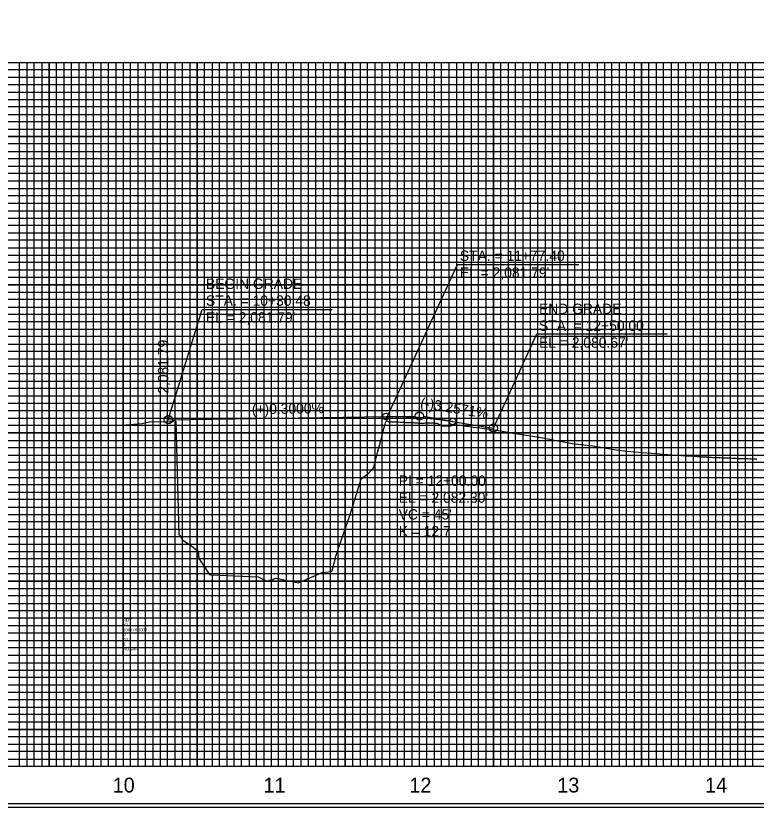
# Model space of a CAD drawing. Extents: x 757145 to 758829, y 592169 to 594973.
# Drawn here: x 757639 to 758139, y 592728 to 593262 of the extents above; entities that cross this region are included whole.
import ezdxf

# ---------------------------------------------------------------- set-up
doc = ezdxf.new("R2010")
doc.units = 0
for name, color, linetype in [('Default', 7, 'Continuous'), ('Exist CMT Alignment Centerline', 7, 'Continuous'), ('Exist CMT EOP', 7, 'Continuous'), ('Exist Vertical Profile Ground Line', 7, 'Continuous'), ('Prop CMT DNC', 7, 'Continuous'), ('Prop Dimension', 7, 'Continuous'), ('Prop Vertical Profile Curve Label', 7, 'Continuous'), ('Prop Vertical Profile Grade Label', 7, 'Continuous'), ('Scratch_Level_4', 7, 'Continuous'), ('Sheet DOT Grid CELL', 7, 'Continuous'), ('Sheet Plan And Profile CELL', 7, 'Continuous'), ('Sheet Plot Border Inside CELL', 7, 'Continuous'), ('Sheet Profile Grid Major CELL', 7, 'Continuous'), ('Sheet Profile Grid Middle CELL', 7, 'Continuous'), ('Sheet Profile Grid Minor CELL', 7, 'Continuous')]:
    doc.layers.add(name, color=color, linetype=linetype)

msp = doc.modelspace()

# ---------------------------------------------------------------- linework, layer by layer
at = {"layer": 'Default'}
for p, q in [((757889.32, 592989.23), (757937.71, 593094.1)), ((757937.71, 593094.1), (758019.68, 593094.1)), ((757742.4, 592989.28), (757765.31, 593063.71)), ((757765.31, 593063.71), (757852.97, 593063.71)), ((757961.92, 592983.68), (757991.19, 593047.13)), ((757991.19, 593047.13), (758079.26, 593047.13)), ((757742.4, 592989.28), (757742.4, 592989.28))]:
    msp.add_line(p, q, dxfattribs=at)
at = {"layer": 'Exist CMT Alignment Centerline'}
for p, q in [((757742.4, 592989.28), (757889.42, 592991.48)), ((757934.42, 592988.15), (757961.92, 592983.68))]:
    msp.add_line(p, q, dxfattribs=at)
msp.add_spline([(757889.42, 592991.48), (757890.32, 592991.49), (757891.22, 592991.5), (757892.12, 592991.51), (757893.02, 592991.51), (757893.92, 592991.51), (757894.82, 592991.5), (757895.72, 592991.5), (757896.62, 592991.49), (757897.52, 592991.47), (757898.42, 592991.46), (757899.32, 592991.44), (757900.22, 592991.41), (757901.12, 592991.39), (757902.02, 592991.36), (757902.92, 592991.32), (757903.82, 592991.29), (757904.72, 592991.25), (757905.62, 592991.21), (757906.52, 592991.16), (757907.42, 592991.11), (757908.32, 592991.06), (757909.22, 592991), (757910.12, 592990.95), (757911.02, 592990.88), (757911.92, 592990.82), (757912.82, 592990.75), (757913.72, 592990.68), (757914.62, 592990.6), (757915.52, 592990.53), (757916.42, 592990.45), (757917.32, 592990.36), (757918.22, 592990.27), (757919.12, 592990.18), (757920.02, 592990.09), (757920.92, 592989.99), (757921.82, 592989.89), (757922.72, 592989.79), (757923.62, 592989.68), (757924.52, 592989.57), (757925.42, 592989.46), (757926.32, 592989.34), (757927.22, 592989.22), (757928.12, 592989.1), (757929.02, 592988.98), (757929.92, 592988.85), (757930.82, 592988.72), (757931.72, 592988.58), (757932.62, 592988.44), (757933.52, 592988.3), (757934.42, 592988.15)], degree=3, dxfattribs=at)
at = {"layer": 'Exist CMT EOP'}
for points in [[(757711.92, 592985.24), (757712.47, 592985.41), (757714.01, 592985.74), (757721.62, 592986.47), (757724.71, 592986.74), (757729.79, 592987.81), (757743.55, 592988.08), (757745.6, 592988.13), (757746.46, 592989.13), (757747.42, 592988.01), (757749.55, 592911.52), (757750.22, 592911.44), (757751.98, 592908.18), (757758.23, 592903.97), (757762.49, 592900.64), (757762.91, 592895.54), (757770.23, 592884.8), (757771.05, 592884.7), (757803.16, 592883.34), (757809.03, 592880.24), (757815.16, 592882.44), (757830.25, 592879.11), (757846.38, 592886.07), (757852.84, 592886.82), (757855.02, 592894.95), (757855.36, 592896.53), (757856.97, 592901.21), (757865.21, 592925.3), (757869.24, 592938.45), (757872.6, 592949.31), (757877.54, 592953.17), (757879.38, 592954.93), (757879.96, 592955.48), (757880.54, 592956.03), (757881.12, 592957.05), (757881.7, 592959.28), (757882.27, 592961.5), (757882.85, 592963.72), (757883.43, 592965.92), (757884.01, 592968.11), (757884.59, 592970.3), (757885.17, 592972.48), (757885.74, 592974.66), (757886.32, 592976.83), (757886.9, 592979), (757887.48, 592981.16), (757888.06, 592983.32), (757888.63, 592985.47), (757889.31, 592987.99), (757889.79, 592988.5), (757890.37, 592988.59), (757890.95, 592987.96), (757891.53, 592987.95), (757892.1, 592987.95), (757892.68, 592987.94), (757893.26, 592987.93), (757893.84, 592987.92), (757894.42, 592987.91), (757895, 592987.91), (757895.57, 592987.9), (757896.15, 592987.89), (757896.73, 592987.88), (757897.31, 592987.87), (757897.89, 592987.82), (757899.04, 592987.62), (757899.62, 592987.59), (757900.2, 592987.56), (757900.78, 592987.53), (757901.36, 592987.52), (757901.93, 592987.5), (757902.51, 592987.49), (757903.09, 592987.47), (757903.67, 592987.46), (757904.25, 592987.44), (757904.83, 592987.43), (757905.4, 592987.41), (757905.98, 592987.39), (757906.56, 592987.37), (757907.14, 592987.35), (757907.72, 592987.33), (757908.29, 592987.29), (757908.87, 592987.25), (757909.45, 592987.21), (757910.03, 592987.16), (757910.61, 592987.12), (757911.19, 592987.08), (757911.76, 592987.04), (757912.34, 592987.03), (757912.92, 592987.03), (757913.5, 592987.02), (757914.08, 592987.01), (757914.66, 592987.03), (757915.23, 592987.05), (757915.81, 592987.06), (757916.41, 592987.08), (757916.97, 592987.11), (757917.55, 592987.14), (757918.12, 592987.16), (757918.7, 592987.19), (757919.28, 592987.22), (757919.86, 592987.25)], [(757919.86, 592987.25), (757920.44, 592987.26), (757921.02, 592987.21), (757921.59, 592987.15), (757922.17, 592987.09), (757922.75, 592987.03), (757923.33, 592986.97), (757923.91, 592986.9), (757924.49, 592986.77), (757925.06, 592986.36), (757925.64, 592985.96), (757926.22, 592985.55), (757926.8, 592985.17), (757927.38, 592985.18), (757927.95, 592985.19), (757928.53, 592985.2), (757929.29, 592985.2), (757929.69, 592985.18), (757930.27, 592985.15), (757930.85, 592985.12), (757931.42, 592985.08), (757932, 592985.04), (757932.63, 592984.99), (757933.16, 592985.19), (757933.74, 592985.41), (757934.31, 592985.62), (757934.89, 592985.83), (757935.57, 592986.08), (757943.88, 592984.89), (757948.27, 592984.28), (757952.74, 592983.71), (757960.6, 592982.59), (757965.23, 592982.05), (757970.61, 592981.17), (757976.76, 592980.02), (757991.42, 592977.65), (758006.74, 592974.78), (758014.32, 592973.55), (758015.23, 592973.3), (758029.13, 592971.56), (758044.8, 592969.03), (758052.32, 592968.1), (758062.65, 592967.11), (758071.74, 592966.57), (758082.42, 592965.54), (758084.2, 592965.43), (758085.75, 592965.34), (758087.3, 592965.25), (758088.84, 592965.16), (758090.39, 592965.06), (758091.19, 592965.02), (758091.93, 592964.98), (758093.48, 592964.89), (758095.03, 592964.81), (758096.57, 592964.72), (758098.12, 592964.6), (758099.67, 592964.48), (758101.21, 592964.35), (758102.18, 592964.28), (758102.76, 592964.25), (758104.3, 592964.18), (758105.85, 592964.12), (758106.17, 592964.1), (758107.4, 592964.04), (758108.94, 592963.96), (758110.49, 592963.88), (758112.03, 592963.81), (758113.58, 592963.76), (758115.13, 592963.71), (758116.67, 592963.66), (758118.22, 592963.61), (758119.77, 592963.54), (758121.31, 592963.47), (758122.86, 592963.4), (758124.4, 592963.33), (758125.95, 592963.25), (758127.5, 592963.18), (758129.04, 592963.11), (758130.59, 592963.08), (758132.14, 592963.05), (758133.68, 592963.02), (758135.39, 592962.98), (758136.77, 592962.97), (758138.32, 592962.95), (758139.87, 592962.93)]]:
    msp.add_lwpolyline(points, dxfattribs=at)
at = {"layer": 'Exist Vertical Profile Ground Line'}
for centre in [(757889.42, 592991.48), (757934.42, 592988.15)]:
    msp.add_circle(centre, 2.25, dxfattribs=at)
at = {"layer": 'Prop Dimension'}
msp.add_lwpolyline([(757361.92, 593230.33), (758761.92, 593230.33), (758761.92, 592755.33), (757361.92, 592755.33)], close=True, dxfattribs=at)
at = {"layer": 'Prop Vertical Profile Grade Label'}
for p, q in [((757889.42, 592991.48), (757909.17, 592991.78)), ((757934.42, 592988.15), (757914.63, 592991.38))]:
    msp.add_line(p, q, dxfattribs=at)
for centre in [(757742.4, 592989.28), (757911.92, 592991.82), (757961.92, 592983.68)]:
    msp.add_circle(centre, 2.75, dxfattribs=at)
at = {"layer": 'Scratch_Level_4'}
for q in [(757711.92, 593080.33), (758636.92, 592830.33), (757711.92, 592830.33)]:
    msp.add_line((757711.92, 592830.33), q, dxfattribs=at)
at = {"layer": 'Sheet DOT Grid CELL'}
for p, q in [((757311.92, 593230.33), (758811.92, 593230.33)), ((757661.92, 593230.33), (757661.92, 592755.33)), ((757711.92, 593230.33), (757711.92, 592755.33)), ((757761.92, 593230.33), (757761.92, 592755.33)), ((757811.92, 593230.33), (757811.92, 592755.33)), ((757861.92, 593230.33), (757861.92, 592755.33)), ((757911.92, 593230.33), (757911.92, 592755.33)), ((757961.92, 593230.33), (757961.92, 592755.33)), ((758011.92, 593230.33), (758011.92, 592755.33)), ((758061.92, 593230.33), (758061.92, 592755.33)), ((758111.92, 593230.33), (758111.92, 592755.33)), ((757311.92, 593180.33), (758811.92, 593180.33)), ((757311.92, 593130.33), (758811.92, 593130.33)), ((757311.92, 593080.33), (758811.92, 593080.33)), ((757311.92, 593030.33), (758811.92, 593030.33)), ((757311.92, 592980.33), (758811.92, 592980.33)), ((757311.92, 592930.33), (758811.92, 592930.33)), ((757311.92, 592880.33), (758811.92, 592880.33)), ((757311.92, 592830.33), (758811.92, 592830.33)), ((757311.92, 592780.33), (758811.92, 592780.33))]:
    msp.add_line(p, q, dxfattribs=at)
at = {"layer": 'Sheet Plan And Profile CELL'}
msp.add_line((758811.92, 592755.33), (757311.92, 592755.33), dxfattribs=at)
msp.add_lwpolyline([(758811.92, 593780.33), (757311.92, 593780.33), (757311.92, 592730.33), (758811.92, 592730.33)], close=True, dxfattribs=at)
at = {"layer": 'Sheet Plot Border Inside CELL'}
msp.add_lwpolyline([(757158.42, 592727.83), (758824.42, 592727.83), (758824.42, 593782.83), (757158.42, 593782.83)], close=True, dxfattribs=at)
at = {"layer": 'Sheet Profile Grid Major CELL'}
for points in [[(757311.92, 593230.33), (758811.92, 593230.33)], [(757661.92, 592755.33), (757661.92, 593230.33), (757711.92, 593230.33), (757711.92, 592755.33)], [(757761.92, 592755.33), (757761.92, 593230.33), (757811.92, 593230.33), (757811.92, 592755.33)], [(757861.92, 592755.33), (757861.92, 593230.33), (757911.92, 593230.33), (757911.92, 592755.33)], [(757961.92, 592755.33), (757961.92, 593230.33), (758011.92, 593230.33), (758011.92, 592755.33)], [(758061.92, 592755.33), (758061.92, 593230.33), (758111.92, 593230.33), (758111.92, 592755.33)], [(758811.92, 593180.33), (757311.92, 593180.33), (757311.92, 593130.33), (758811.92, 593130.33)], [(758811.92, 593080.33), (757311.92, 593080.33), (757311.92, 593030.33), (758811.92, 593030.33)], [(758811.92, 592980.33), (757311.92, 592980.33), (757311.92, 592930.33), (758811.92, 592930.33)], [(758811.92, 592880.33), (757311.92, 592880.33), (757311.92, 592830.33), (758811.92, 592830.33)], [(758811.92, 592780.33), (757311.92, 592780.33)]]:
    msp.add_lwpolyline(points, dxfattribs=at)
at = {"layer": 'Sheet Profile Grid Middle CELL'}
for p, q in [((757311.92, 593205.33), (758811.92, 593205.33)), ((758811.92, 593155.33), (757311.92, 593155.33)), ((757311.92, 593105.33), (758811.92, 593105.33)), ((758811.92, 593055.33), (757311.92, 593055.33)), ((757311.92, 593005.33), (758811.92, 593005.33)), ((758811.92, 592955.33), (757311.92, 592955.33)), ((757311.92, 592905.33), (758811.92, 592905.33)), ((758811.92, 592855.33), (757311.92, 592855.33)), ((757311.92, 592805.33), (758811.92, 592805.33))]:
    msp.add_line(p, q, dxfattribs=at)
for points in [[(757686.92, 592755.33), (757686.92, 593230.33), (757736.92, 593230.33), (757736.92, 592755.33)], [(757786.92, 592755.33), (757786.92, 593230.33), (757836.92, 593230.33), (757836.92, 592755.33)], [(757886.92, 592755.33), (757886.92, 593230.33), (757936.92, 593230.33), (757936.92, 592755.33)], [(757986.92, 592755.33), (757986.92, 593230.33), (758036.92, 593230.33), (758036.92, 592755.33)], [(758086.92, 592755.33), (758086.92, 593230.33), (758136.92, 593230.33), (758136.92, 592755.33)]]:
    msp.add_lwpolyline(points, dxfattribs=at)
at = {"layer": 'Sheet Profile Grid Minor CELL'}
for points in [[(757641.92, 592755.33), (757641.92, 593230.33), (757646.92, 593230.33), (757646.92, 592755.33)], [(757651.92, 592755.33), (757651.92, 593230.33), (757656.92, 593230.33), (757656.92, 592755.33)], [(757666.92, 592755.33), (757666.92, 593230.33), (757671.92, 593230.33), (757671.92, 592755.33)], [(757676.92, 592755.33), (757676.92, 593230.33), (757681.92, 593230.33), (757681.92, 592755.33)], [(757691.92, 592755.33), (757691.92, 593230.33), (757696.92, 593230.33), (757696.92, 592755.33)], [(757701.92, 592755.33), (757701.92, 593230.33), (757706.92, 593230.33), (757706.92, 592755.33)], [(757716.92, 592755.33), (757716.92, 593230.33), (757721.92, 593230.33), (757721.92, 592755.33)], [(757726.92, 592755.33), (757726.92, 593230.33), (757731.92, 593230.33), (757731.92, 592755.33)], [(757741.92, 592755.33), (757741.92, 593230.33), (757746.92, 593230.33), (757746.92, 592755.33)], [(757751.92, 592755.33), (757751.92, 593230.33), (757756.92, 593230.33), (757756.92, 592755.33)], [(757766.92, 592755.33), (757766.92, 593230.33), (757771.92, 593230.33), (757771.92, 592755.33)], [(757776.92, 592755.33), (757776.92, 593230.33), (757781.92, 593230.33), (757781.92, 592755.33)], [(757791.92, 592755.33), (757791.92, 593230.33), (757796.92, 593230.33), (757796.92, 592755.33)], [(757801.92, 592755.33), (757801.92, 593230.33), (757806.92, 593230.33), (757806.92, 592755.33)], [(757816.92, 592755.33), (757816.92, 593230.33), (757821.92, 593230.33), (757821.92, 592755.33)], [(757826.92, 592755.33), (757826.92, 593230.33), (757831.92, 593230.33), (757831.92, 592755.33)], [(757841.92, 592755.33), (757841.92, 593230.33), (757846.92, 593230.33), (757846.92, 592755.33)], [(757851.92, 592755.33), (757851.92, 593230.33), (757856.92, 593230.33), (757856.92, 592755.33)], [(757866.92, 592755.33), (757866.92, 593230.33), (757871.92, 593230.33), (757871.92, 592755.33)], [(757876.92, 592755.33), (757876.92, 593230.33), (757881.92, 593230.33), (757881.92, 592755.33)], [(757891.92, 592755.33), (757891.92, 593230.33), (757896.92, 593230.33), (757896.92, 592755.33)], [(757901.92, 592755.33), (757901.92, 593230.33), (757906.92, 593230.33), (757906.92, 592755.33)], [(757916.92, 592755.33), (757916.92, 593230.33), (757921.92, 593230.33), (757921.92, 592755.33)], [(757926.92, 592755.33), (757926.92, 593230.33), (757931.92, 593230.33), (757931.92, 592755.33)], [(757941.92, 592755.33), (757941.92, 593230.33), (757946.92, 593230.33), (757946.92, 592755.33)], [(757951.92, 592755.33), (757951.92, 593230.33), (757956.92, 593230.33), (757956.92, 592755.33)], [(757966.92, 592755.33), (757966.92, 593230.33), (757971.92, 593230.33), (757971.92, 592755.33)], [(757976.92, 592755.33), (757976.92, 593230.33), (757981.92, 593230.33), (757981.92, 592755.33)], [(757991.92, 592755.33), (757991.92, 593230.33), (757996.92, 593230.33), (757996.92, 592755.33)], [(758001.92, 592755.33), (758001.92, 593230.33), (758006.92, 593230.33), (758006.92, 592755.33)], [(758016.92, 592755.33), (758016.92, 593230.33), (758021.92, 593230.33), (758021.92, 592755.33)], [(758026.92, 592755.33), (758026.92, 593230.33), (758031.92, 593230.33), (758031.92, 592755.33)], [(758041.92, 592755.33), (758041.92, 593230.33), (758046.92, 593230.33), (758046.92, 592755.33)], [(758051.92, 592755.33), (758051.92, 593230.33), (758056.92, 593230.33), (758056.92, 592755.33)], [(758066.92, 592755.33), (758066.92, 593230.33), (758071.92, 593230.33), (758071.92, 592755.33)], [(758076.92, 592755.33), (758076.92, 593230.33), (758081.92, 593230.33), (758081.92, 592755.33)], [(758091.92, 592755.33), (758091.92, 593230.33), (758096.92, 593230.33), (758096.92, 592755.33)], [(758101.92, 592755.33), (758101.92, 593230.33), (758106.92, 593230.33), (758106.92, 592755.33)], [(758116.92, 592755.33), (758116.92, 593230.33), (758121.92, 593230.33), (758121.92, 592755.33)], [(758126.92, 592755.33), (758126.92, 593230.33), (758131.92, 593230.33), (758131.92, 592755.33)], [(758761.92, 593225.33), (757361.92, 593225.33)], [(758761.92, 593215.33), (757361.92, 593215.33), (757361.92, 593220.33), (758761.92, 593220.33)], [(758761.92, 593200.33), (757361.92, 593200.33), (757361.92, 593205.33), (757361.92, 593210.33), (758761.92, 593210.33)], [(758761.92, 593190.33), (757361.92, 593190.33), (757361.92, 593195.33), (758761.92, 593195.33)], [(758761.92, 593175.33), (757361.92, 593175.33), (757361.92, 593180.33), (757361.92, 593185.33), (758761.92, 593185.33)], [(758761.92, 593165.33), (757361.92, 593165.33), (757361.92, 593170.33), (758761.92, 593170.33)], [(758761.92, 593150.33), (757361.92, 593150.33), (757361.92, 593155.33), (757361.92, 593160.33), (758761.92, 593160.33)], [(758761.92, 593140.33), (757361.92, 593140.33), (757361.92, 593145.33), (758761.92, 593145.33)], [(757361.92, 593125.33), (757361.92, 593130.33), (757361.92, 593135.33), (758761.92, 593135.33)], [(758761.92, 593120.33), (757361.92, 593120.33), (757361.92, 593125.33), (758761.92, 593125.33)], [(758761.92, 593110.33), (757361.92, 593110.33), (757361.92, 593115.33), (758761.92, 593115.33)], [(758761.92, 593095.33), (757361.92, 593095.33), (757361.92, 593100.33), (758761.92, 593100.33)], [(758761.92, 593085.33), (757361.92, 593085.33), (757361.92, 593090.33), (758761.92, 593090.33)], [(758761.92, 593070.33), (757361.92, 593070.33), (757361.92, 593075.33), (758761.92, 593075.33)], [(758761.92, 593060.33), (757361.92, 593060.33), (757361.92, 593065.33), (758761.92, 593065.33)], [(758761.92, 593045.33), (757361.92, 593045.33), (757361.92, 593050.33), (758761.92, 593050.33)], [(758761.92, 593035.33), (757361.92, 593035.33), (757361.92, 593040.33), (758761.92, 593040.33)], [(758761.92, 593020.33), (757361.92, 593020.33), (757361.92, 593025.33), (758761.92, 593025.33)], [(758761.92, 593010.33), (757361.92, 593010.33), (757361.92, 593015.33), (758761.92, 593015.33)], [(758761.92, 592995.33), (757361.92, 592995.33), (757361.92, 593000.33), (758761.92, 593000.33)], [(758761.92, 592985.33), (757361.92, 592985.33), (757361.92, 592990.33), (758761.92, 592990.33)], [(758761.92, 592970.33), (757361.92, 592970.33), (757361.92, 592975.33), (758761.92, 592975.33)], [(758761.92, 592960.33), (757361.92, 592960.33), (757361.92, 592965.33), (758761.92, 592965.33)], [(758761.92, 592945.33), (757361.92, 592945.33), (757361.92, 592950.33), (758761.92, 592950.33)], [(758761.92, 592935.33), (757361.92, 592935.33), (757361.92, 592940.33), (758761.92, 592940.33)], [(758761.92, 592920.33), (757361.92, 592920.33), (757361.92, 592925.33), (758761.92, 592925.33)], [(758761.92, 592910.33), (757361.92, 592910.33), (757361.92, 592915.33), (758761.92, 592915.33)], [(758761.92, 592895.33), (757361.92, 592895.33), (757361.92, 592900.33), (758761.92, 592900.33)], [(758761.92, 592885.33), (757361.92, 592885.33), (757361.92, 592890.33), (758761.92, 592890.33)], [(758761.92, 592870.33), (757361.92, 592870.33), (757361.92, 592875.33), (758761.92, 592875.33)], [(758761.92, 592860.33), (757361.92, 592860.33), (757361.92, 592865.33), (758761.92, 592865.33)], [(758761.92, 592845.33), (757361.92, 592845.33), (757361.92, 592850.33), (758761.92, 592850.33)], [(758761.92, 592835.33), (757361.92, 592835.33), (757361.92, 592840.33), (758761.92, 592840.33)], [(757361.92, 592820.33), (757361.92, 592825.33), (758761.92, 592825.33)], [(757361.92, 592760.33), (758761.92, 592760.33), (758761.92, 592765.33), (757361.92, 592765.33), (757361.92, 592770.33), (758761.92, 592770.33), (758761.92, 592775.33), (757361.92, 592775.33), (757361.92, 592780.33), (757361.92, 592785.33), (758761.92, 592785.33), (758761.92, 592790.33), (757361.92, 592790.33), (757361.92, 592795.33), (758761.92, 592795.33), (758761.92, 592800.33), (757361.92, 592800.33), (757361.92, 592805.33), (757361.92, 592810.33), (758761.92, 592810.33), (758761.92, 592815.33), (757361.92, 592815.33), (757361.92, 592820.33), (758761.92, 592820.33)]]:
    msp.add_lwpolyline(points, dxfattribs=at)

# ---------------------------------------------------------------- texts
at = {"layer": 'Default'}
for s, p in [('STA. = 11+77.40', (757939.33, 593096.42)), ("EL = 2,081.79'", (757939.33, 593085.05)), ('BEGIN GRADE', (757767.83, 593077.54)), ('STA. = 10+30.48', (757767.83, 593066.16)), ('END GRADE', (757992.77, 593060.61)), ("EL = 2,081.79'", (757767.83, 593054.79)), ('STA. = 12+50.00', (757992.77, 593049.24)), ("EL = 2,080.67'", (757992.77, 593037.86))]:
    msp.add_text(s, height=7, dxfattribs=at).set_placement(p)
at = {"layer": 'Prop CMT DNC'}
for s, p in [('10', (757704.84, 592737.72)), ('11', (757806.68, 592737.72)), ('12', (757905.23, 592737.72)), ('13', (758005.07, 592737.72)), ('14', (758104.91, 592737.72))]:
    msp.add_text(s, height=10, dxfattribs=at).set_placement(p)
at = {"layer": 'Prop Vertical Profile Curve Label'}
for s, rotation, p in [('(-)3.2571%', 350.7502, (757912.19, 592997.4)), ('(+)0.3000%', 0.8594, (757798.85, 592992.94))]:
    msp.add_text(s, height=7, rotation=rotation, dxfattribs=at).set_placement(p)
at = {"layer": 'Prop Vertical Profile Grade Label'}
msp.add_text('2,081.79', height=7, rotation=90, dxfattribs=at).set_placement((757742.4, 593006.78))
for s, p in [('PI = 12+00.00', (757898, 592944.64)), ("EL = 2,082.30'", (757898, 592933.26)), ("VC = 45'", (757898, 592921.89)), ('K = 12.7', (757898, 592910.51))]:
    msp.add_text(s, height=7, dxfattribs=at).set_placement(p)
at = {"layer": 'Scratch_Level_4'}
for s, p in [('Y1', (757711.92, 592849.83)), ('RDY', (757711.92, 592853.08)), ('1000.000000', (757711.92, 592846.58)), ('0', (757711.92, 592843.33)), ('10', (757711.92, 592840.08)), ('2', (757711.92, 592836.83)), ('NOGAP', (757711.92, 592833.58))]:
    msp.add_text(s, height=2, dxfattribs=at).set_placement(p)

doc.saveas('drawing.dxf')
